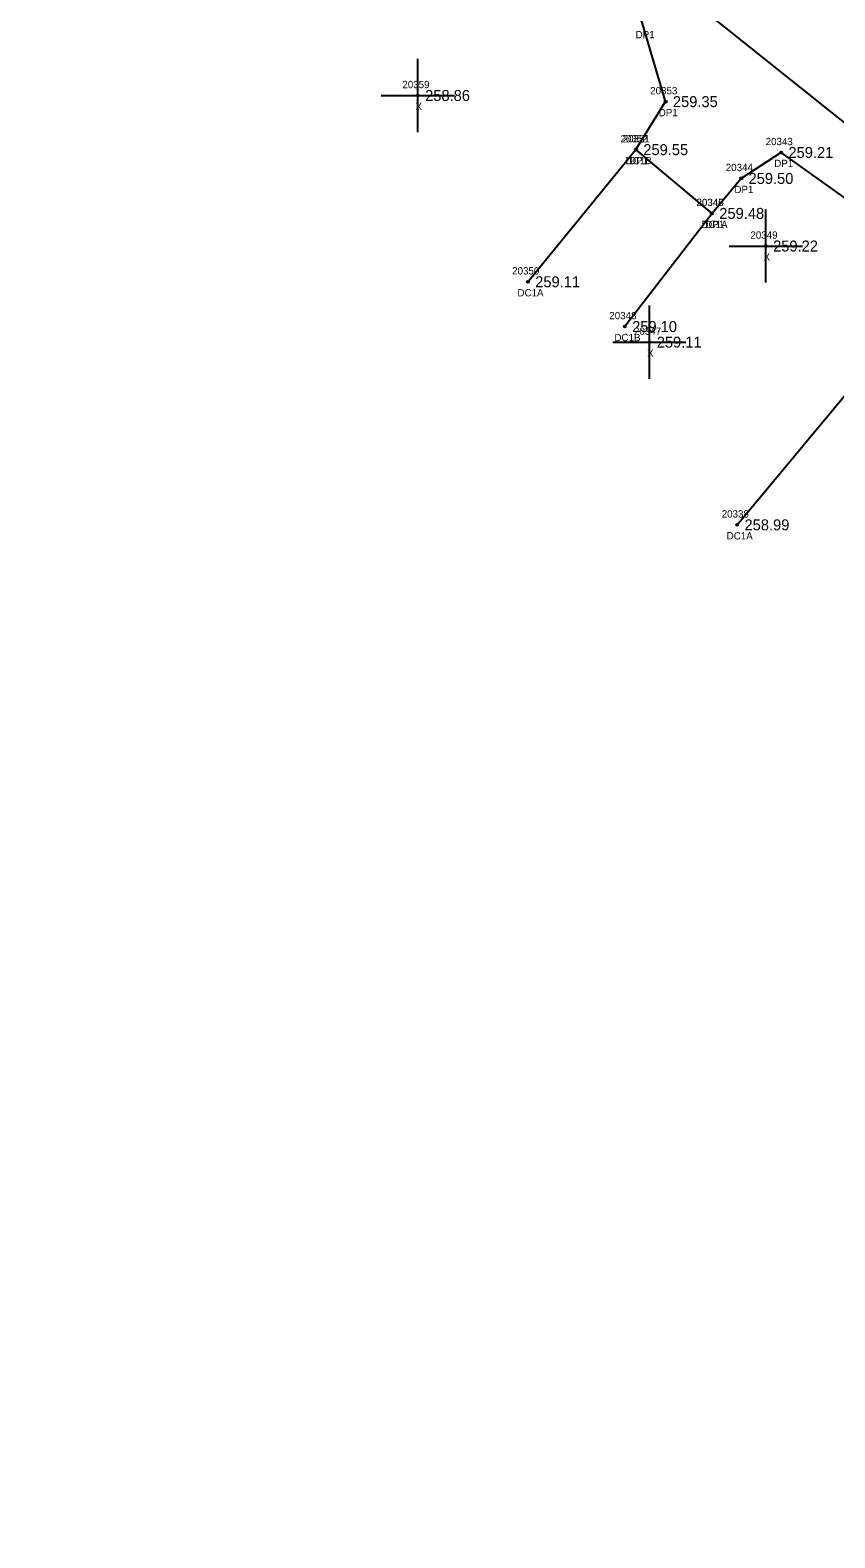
# Model space of a CAD drawing. Extents: x 1961330 to 1962287, y 800294 to 801079.
# Drawn here: x 1961649 to 1961759.1, y 800521.8 to 800727.9 of the extents above; entities that cross this region are included whole.
import ezdxf

# ---------------------------------------------------------------- set-up
doc = ezdxf.new("R2010")
doc.units = 0
for name, color, linetype in [('RD_EX_Conc', 7, 'Continuous'), ('RD_EX_Conc_txCode', 7, 'Continuous'), ('RD_EX_Driveway', 7, 'Continuous'), ('RD_EX_Driveway_txCode', 7, 'Continuous'), ('RD_EX_Misc', 7, 'Continuous'), ('RD_EX_Misc_txCode', 7, 'Continuous'), ('RD_EX_Road', 7, 'Continuous'), ('RD_EX_TX_Conc_ELEV', 7, 'Continuous'), ('RD_EX_TX_Driveway_ELEV', 7, 'Continuous'), ('RD_EX_TX_Misc_ELEV', 7, 'Continuous'), ('RD_SMD_Locator', 7, 'Continuous')]:
    doc.layers.add(name, color=color, linetype=linetype)

msp = doc.modelspace()

# ---------------------------------------------------------------- linework, layer by layer
at = {"layer": 'RD_EX_Conc'}
for p, q in [((1961717.1, 800693.53), (1961731.89, 800711.6)), ((1961742.29, 800702.88), (1961730.36, 800687.41)), ((1961745.74, 800660.3), (1961765.27, 800683.8))]:
    msp.add_line(p, q, dxfattribs=at)
at = {"layer": 'RD_EX_Driveway'}
msp.add_lwpolyline([(1961801.42, 800682.57), (1961792.79, 800679.78), (1961785.2, 800682.11), (1961781.31, 800680.84), (1961776.43, 800674.97), (1961765.27, 800683.8), (1961771.82, 800693.99), (1961761.47, 800704.29), (1961751.75, 800711.21), (1961746.29, 800707.66), (1961742.29, 800702.88), (1961731.89, 800711.6), (1961735.94, 800718.16), (1961732.79, 800728.82), (1961728.41, 800740.86)], dxfattribs=at)
at = {"layer": 'RD_EX_Misc'}
for p, q in [((1961702.04, 800714), (1961702.04, 800724)), ((1961697.04, 800719), (1961707.04, 800719)), ((1961749.65, 800693.42), (1961749.65, 800703.42)), ((1961744.65, 800698.42), (1961754.65, 800698.42)), ((1961733.73, 800680.28), (1961733.73, 800690.28)), ((1961728.73, 800685.28), (1961738.73, 800685.28))]:
    msp.add_line(p, q, dxfattribs=at)
at = {"layer": 'RD_EX_Road'}
msp.add_lwpolyline([(1962241.79, 800315.68), (1962238.35, 800317.6), (1962189.92, 800352.69), (1962151.64, 800383.49), (1962113.78, 800416.39), (1962074.11, 800451.29), (1962034.78, 800486.96), (1962017.07, 800503.17), (1961999.46, 800519.25), (1961962.48, 800552.12), (1961937.08, 800573.11), (1961923.19, 800584.9), (1961883.07, 800617.43), (1961838.29, 800653.43), (1961801.42, 800682.57), (1961728.41, 800740.86), (1961722.95, 800745.11), (1961689.13, 800771.93), (1961670.14, 800787.03), (1961660.52, 800795.31), (1961637.49, 800813.67)], dxfattribs=at)
at = {"layer": 'RD_SMD_Locator'}
for centre in [(1961702.04, 800719), (1961735.94, 800718.16), (1961731.89, 800711.6), (1961731.89, 800711.6), (1961751.75, 800711.21), (1961746.29, 800707.66), (1961742.29, 800702.88), (1961742.29, 800702.88), (1961749.65, 800698.42), (1961717.1, 800693.53), (1961730.36, 800687.41), (1961733.73, 800685.28), (1961745.74, 800660.3)]:
    msp.add_circle(centre, 0.15, dxfattribs=at)

# ---------------------------------------------------------------- texts
at = {"layer": 'RD_EX_Conc_txCode'}
for s, p in [('20351', (1961730.06, 800712.6)), ('DC1B', (1961730.48, 800709.6)), ('20346', (1961740.15, 800703.88)), ('DC1A', (1961740.86, 800700.88)), ('20350', (1961714.94, 800694.53)), ('DC1A', (1961715.67, 800691.53)), ('20348', (1961728.24, 800688.41)), ('DC1B', (1961728.94, 800685.41)), ('20338', (1961743.62, 800661.3)), ('DC1A', (1961744.3, 800658.3))]:
    msp.add_text(s, height=1, dxfattribs=at).set_placement(p)
at = {"layer": 'RD_EX_Driveway_txCode'}
for s, p in [('DP1', (1961731.84, 800726.82)), ('20353', (1961733.83, 800719.16)), ('DP1', (1961735, 800716.16)), ('20352', (1961729.78, 800712.6)), ('20343', (1961749.63, 800712.21)), ('DP1', (1961730.95, 800709.6)), ('DP1', (1961750.8, 800709.21)), ('20344', (1961744.17, 800708.66)), ('DP1', (1961745.35, 800705.66)), ('20345', (1961740.17, 800703.88)), ('DP1', (1961741.35, 800700.88))]:
    msp.add_text(s, height=1, dxfattribs=at).set_placement(p)
at = {"layer": 'RD_EX_Misc_txCode'}
for s, p in [('20359', (1961699.92, 800720)), ('X', (1961701.72, 800717)), ('20349', (1961747.54, 800699.42)), ('X', (1961749.34, 800696.42)), ('20347', (1961731.61, 800686.28)), ('X', (1961733.41, 800683.28))]:
    msp.add_text(s, height=1, dxfattribs=at).set_placement(p)
at = {"layer": 'RD_EX_TX_Conc_ELEV'}
for s, p in [('259.55', (1961732.89, 800710.85)), ('259.48', (1961743.29, 800702.13)), ('259.11', (1961718.1, 800692.78)), ('259.10', (1961731.36, 800686.66)), ('258.99', (1961746.74, 800659.55))]:
    msp.add_text(s, height=1.5, dxfattribs=at).set_placement(p)
at = {"layer": 'RD_EX_TX_Driveway_ELEV'}
for s, p in [('259.35', (1961736.94, 800717.41)), ('259.55', (1961732.89, 800710.85)), ('259.21', (1961752.75, 800710.46)), ('259.50', (1961747.29, 800706.91)), ('259.48', (1961743.29, 800702.13))]:
    msp.add_text(s, height=1.5, dxfattribs=at).set_placement(p)
at = {"layer": 'RD_EX_TX_Misc_ELEV'}
for s, p in [('258.86', (1961703.04, 800718.25)), ('259.22', (1961750.65, 800697.67)), ('259.11', (1961734.73, 800684.53))]:
    msp.add_text(s, height=1.5, dxfattribs=at).set_placement(p)

doc.saveas('drawing.dxf')
